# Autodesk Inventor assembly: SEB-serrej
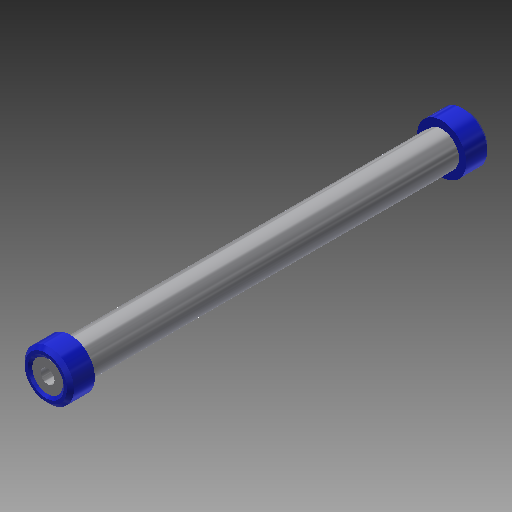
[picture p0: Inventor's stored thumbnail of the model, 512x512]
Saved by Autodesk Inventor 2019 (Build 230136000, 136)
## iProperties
Created: 2019-02
Part Number: SEB-serrej
Material: Générique
Document SubType Name: Assembly
Designer: si-nd67
Mass: 10.1994 g
Surface Area: 52.2957 cm^2
Volume: 10.1994 cm^3
Density: 1 g/cm^3
Author: si-nd67
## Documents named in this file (3)
- E:\ECAM\serrejointsw\SEB-serrej.iam
- E:\ECAM\serrejointsw\tige14.ipt
- E:\ECAM\serrejointsw\Embout14.ipt
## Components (3 placed, 2 different names)
1. tige14:1 — Logement:1, Logement:2
2. Embout14:1 — Logement:1
3. Embout14:2 — Logement:2
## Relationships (2: Insert 2)
- Logement:1 [Insert]: tige14:1 ↔ Embout14:1
- Logement:2 [Insert]: tige14:1 ↔ Embout14:2
